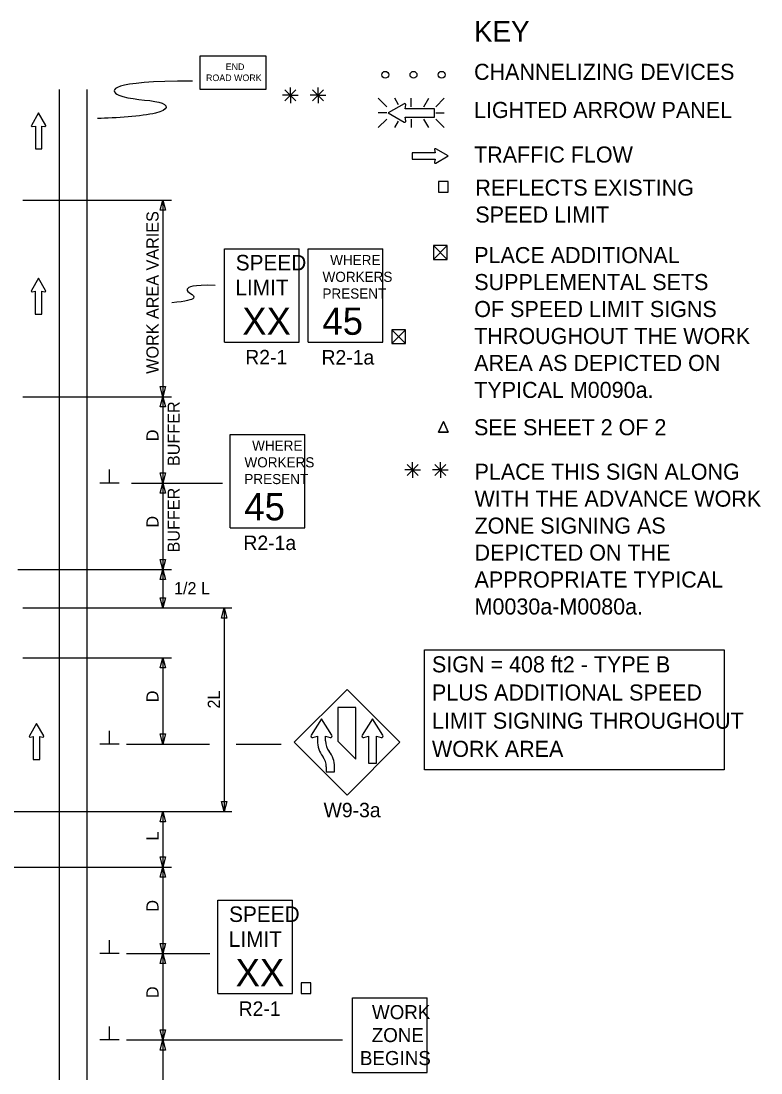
# Model space of a CAD drawing. Extents: x 16728 to 18482, y 5716 to 6919.
# Drawn here: x 17004 to 17432, y 6311 to 6919 of the extents above; entities that cross this region are included whole.
import ezdxf

# ---------------------------------------------------------------- set-up
doc = ezdxf.new("R2010")
doc.units = 0
for name, color, linetype in [('MT_SCRATCH_LEVEL_E', 7, 'Continuous'), ('PAVT_EDGE_EX', 7, 'Continuous'), ('TRAFFIC_SIGNS_PR', 7, 'Continuous'), ('TYPICAL_TEXT_DIMEN_EX', 7, 'Continuous'), ('TYPICAL_TEXT_DIMEN_PR', 7, 'Continuous')]:
    doc.layers.add(name, color=color, linetype=linetype)

msp = doc.modelspace()

# ---------------------------------------------------------------- linework, layer by layer
at = {"layer": 'MT_SCRATCH_LEVEL_E'}
for p, q in [((17014.23, 6866.09), (17010.12, 6858.85)), ((17018.37, 6858.85), (17014.23, 6866.09)), ((17010.6, 6858.17), (17012.38, 6858.48)), ((17012.38, 6858.48), (17012.38, 6845.23)), ((17016.12, 6845.23), (17016.12, 6858.48)), ((17016.12, 6858.48), (17017.9, 6858.17)), ((17012.38, 6845.23), (17016.12, 6845.23)), ((17243.66, 6843.03), (17230.4, 6843.03)), ((17230.4, 6843.03), (17230.4, 6839.29)), ((17243.34, 6844.81), (17243.66, 6843.03)), ((17251.27, 6841.18), (17244.03, 6845.29)), ((17230.4, 6839.29), (17243.66, 6839.29)), ((17243.66, 6839.29), (17243.34, 6837.51)), ((17244.03, 6837.03), (17251.27, 6841.18)), ((17014.19, 6770.46), (17010.08, 6763.22)), ((17018.34, 6763.22), (17014.19, 6770.46)), ((17010.56, 6762.53), (17012.34, 6762.85)), ((17012.34, 6762.85), (17012.34, 6749.59)), ((17016.08, 6749.59), (17016.08, 6762.85)), ((17016.08, 6762.85), (17017.86, 6762.53)), ((17012.34, 6749.59), (17016.08, 6749.59)), ((17013.05, 6512.79), (17008.94, 6505.55)), ((17017.2, 6505.55), (17013.05, 6512.79)), ((17009.42, 6504.87), (17011.2, 6505.19)), ((17011.2, 6505.19), (17011.2, 6491.93)), ((17014.94, 6491.93), (17014.94, 6505.19)), ((17014.94, 6505.19), (17016.72, 6504.87)), ((17011.2, 6491.93), (17014.94, 6491.93))]:
    msp.add_line(p, q, dxfattribs=at)
for centre, start, end in [((17010.52, 6858.63), 150.42484, 279.96381), ((17017.96, 6858.63), 260.03619, 29.77312), ((17243.8, 6844.88), 60.42484, 189.96381), ((17243.8, 6837.44), 170.03619, 299.77312), ((17010.49, 6762.99), 150.42484, 279.96381), ((17017.93, 6762.99), 260.03619, 29.77312), ((17009.35, 6505.33), 150.42484, 279.96381), ((17016.79, 6505.33), 260.03619, 29.77312)]:
    msp.add_arc(centre, 0.463, start, end, dxfattribs=at)
at = {"layer": 'PAVT_EDGE_EX'}
for p, q in [((17026.2, 6879.62), (17026.2, 6061.48)), ((17042.2, 6879.62), (17042.2, 6061.48))]:
    msp.add_line(p, q, dxfattribs=at)
at = {"layer": 'TRAFFIC_SIGNS_PR'}
for p, q in [((17210.76, 6874.56), (17215.69, 6869.63)), ((17222.52, 6870.74), (17220.32, 6874.57)), ((17229.84, 6869.63), (17229.84, 6874.57)), ((17237.08, 6869.63), (17239.93, 6874.57)), ((17243.99, 6869.63), (17248.93, 6874.57)), ((17215.69, 6866.08), (17210.76, 6866.08)), ((17243.99, 6866.08), (17248.93, 6866.08)), ((17210.76, 6857.59), (17215.69, 6862.52)), ((17220.27, 6857.59), (17222.39, 6861.25)), ((17229.84, 6862.52), (17229.84, 6857.59)), ((17239.97, 6857.59), (17237.12, 6862.52)), ((17243.99, 6862.52), (17248.93, 6857.58)), ((17121.81, 6787.43), (17165.01, 6787.43)), ((17121.81, 6733.43), (17121.81, 6787.43)), ((17165.01, 6733.43), (17165.01, 6787.43)), ((17170.22, 6787.32), (17213.42, 6787.32)), ((17170.22, 6733.32), (17170.22, 6787.32)), ((17213.42, 6733.32), (17213.42, 6787.32)), ((17121.81, 6733.43), (17165.01, 6733.43)), ((17170.22, 6733.32), (17213.42, 6733.32)), ((17125.05, 6679.98), (17168.25, 6679.98)), ((17125.05, 6625.98), (17125.05, 6679.98)), ((17168.25, 6625.98), (17168.25, 6679.98)), ((17125.05, 6625.98), (17168.25, 6625.98)), ((17192.71, 6532.45), (17162.17, 6501.9)), ((17223.26, 6501.9), (17192.71, 6532.45)), ((17187.41, 6522.07), (17187.41, 6502.5)), ((17197.77, 6522.07), (17187.41, 6522.07)), ((17197.77, 6492.14), (17197.77, 6522.07)), ((17162.17, 6501.9), (17192.71, 6471.35)), ((17187.41, 6502.5), (17197.77, 6492.14)), ((17192.71, 6471.35), (17223.26, 6501.9)), ((17117.97, 6410.43), (17161.17, 6410.43)), ((17117.97, 6356.43), (17117.97, 6410.43)), ((17161.17, 6356.43), (17161.17, 6410.43)), ((17117.97, 6356.43), (17161.17, 6356.43)), ((17195.86, 6310.89), (17195.86, 6354.09)), ((17195.86, 6354.09), (17239.06, 6354.09)), ((17239.06, 6310.89), (17239.06, 6354.09)), ((17195.86, 6310.89), (17239.06, 6310.89))]:
    msp.add_line(p, q, dxfattribs=at)
for points in [[(17107.51, 6879.72), (17145.91, 6879.72), (17145.91, 6898.92), (17107.51, 6898.92)], [(17245.62, 6820.15), (17251.21, 6820.15), (17251.21, 6826.32), (17245.62, 6826.32)], [(17166.19, 6356.43), (17171.78, 6356.43), (17171.78, 6362.6), (17166.19, 6362.6)]]:
    msp.add_lwpolyline(points, close=True, dxfattribs=at)
for points in [[(17225.77, 6871.35), (17216.48, 6866.08), (17225.77, 6860.75)], [(17226.65, 6861.38), (17226.25, 6863.65), (17243.26, 6863.65), (17243.26, 6868.45), (17226.25, 6868.45), (17226.65, 6870.73)], [(17248.42, 6687.54), (17245.63, 6681.37)], [(17245.63, 6681.37), (17248.42, 6687.54)], [(17251.22, 6681.37), (17248.42, 6687.54)], [(17248.42, 6687.54), (17251.22, 6681.37)], [(17245.63, 6681.37), (17251.22, 6681.37)], [(17251.22, 6681.37), (17245.63, 6681.37)], [(17183.93, 6506.07), (17177.94, 6515.48), (17171.95, 6506.07)], [(17213.43, 6506.07), (17207.45, 6515.48), (17201.45, 6506.07)], [(17172.99, 6504.65), (17175.58, 6505.36), (17175.57, 6502.85)], [(17180.29, 6502.73), (17180.3, 6505.36), (17182.88, 6504.65)], [(17202.5, 6504.65), (17205.09, 6505.36), (17205.09, 6489.83), (17209.81, 6489.83), (17209.81, 6505.36), (17212.39, 6504.65)], [(17180.71, 6487.71), (17180.71, 6484.73), (17185.43, 6484.73), (17185.43, 6487.71)]]:
    msp.add_lwpolyline(points, dxfattribs=at)
for centre in [(17214.83, 6888.11), (17231.13, 6888.11), (17247.43, 6888.11)]:
    msp.add_circle(centre, 2, dxfattribs=at)
for centre, radius, start, end in [((17226.06, 6870.83), 0.598, 350.73078, 118.89165), ((17226.06, 6861.28), 0.597, 241.48329, 9.95933), ((17172.74, 6505.56), 0.945, 147.52044, 285.3986), ((17189.74, 6502.43), 14.17, 178.32933, 218.54273), ((17168.48, 6503.1), 11.81, 358.18937, 0.00483), ((17189.74, 6502.43), 9.45, 178.19356, 218.54646), ((17183.13, 6505.56), 0.947, 254.68281, 32.2708), ((17179.76, 6493.25), 11.81, 74.67996, 74.68078), ((17193.89, 6512.4), 11.81, 212.45689, 212.46649), ((17202.25, 6505.56), 0.946, 147.54971, 285.33159), ((17212.64, 6505.56), 0.943, 254.67777, 32.46648), ((17223.4, 6512.4), 11.81, 212.45689, 212.46649), ((17171.26, 6487.71), 14.17, 0, 38.5422), ((17171.26, 6487.71), 9.45, 0, 38.54567)]:
    msp.add_arc(centre, radius, start, end, dxfattribs=at)
at = {"layer": 'TYPICAL_TEXT_DIMEN_EX'}
msp.add_lwpolyline([(17237.59, 6555.39), (17410.81, 6555.39), (17410.81, 6485.93), (17237.59, 6485.93)], close=True, dxfattribs=at)
at = {"layer": 'TYPICAL_TEXT_DIMEN_PR'}
for p, q in [((17156.71, 6879.43), (17163.09, 6873.05)), ((17163.09, 6879.43), (17156.71, 6873.05)), ((17159.9, 6876.24), (17159.9, 6880.69)), ((17172.78, 6879.43), (17179.15, 6873.05)), ((17179.15, 6879.43), (17172.78, 6873.05)), ((17175.96, 6876.24), (17175.96, 6880.69)), ((17159.9, 6876.24), (17155.37, 6876.24)), ((17159.9, 6876.24), (17163.09, 6876.24)), ((17159.9, 6876.24), (17164.38, 6876.24)), ((17159.9, 6876.24), (17159.9, 6871.74)), ((17175.96, 6876.24), (17171.43, 6876.24)), ((17175.96, 6876.24), (17179.15, 6876.24)), ((17175.96, 6876.24), (17180.44, 6876.24)), ((17175.96, 6876.24), (17175.96, 6871.74)), ((17005.13, 6815.59), (17091.2, 6815.59)), ((17084.63, 6809.72), (17086.2, 6815.59)), ((17086.2, 6815.59), (17086.2, 6701.86)), ((17086.2, 6815.59), (17087.77, 6809.72)), ((17086.2, 6809.72), (17084.63, 6809.72)), ((17087.77, 6809.72), (17086.2, 6809.72)), ((17242.63, 6789.28), (17250.63, 6781.28)), ((17242.63, 6781.28), (17250.63, 6789.28)), ((17218.57, 6732.53), (17226.57, 6740.53)), ((17218.58, 6740.53), (17226.57, 6732.53)), ((17005.13, 6701.86), (17091.2, 6701.86)), ((17086.2, 6701.86), (17084.63, 6707.72)), ((17084.63, 6707.72), (17086.2, 6707.72)), ((17084.63, 6696), (17086.2, 6701.86)), ((17086.2, 6707.72), (17087.77, 6707.72)), ((17087.77, 6707.72), (17086.2, 6701.86)), ((17086.2, 6701.86), (17086.2, 6651.86)), ((17086.2, 6701.86), (17087.77, 6696)), ((17086.2, 6696), (17084.63, 6696)), ((17087.77, 6696), (17086.2, 6696)), ((17055.32, 6651.86), (17055.32, 6659.65)), ((17230.63, 6659.45), (17226.1, 6659.45)), ((17227.44, 6662.63), (17233.82, 6656.26)), ((17233.82, 6662.63), (17227.44, 6656.26)), ((17230.63, 6659.45), (17230.63, 6663.9)), ((17230.63, 6659.45), (17233.82, 6659.45)), ((17230.63, 6659.45), (17235.11, 6659.45)), ((17230.63, 6659.45), (17230.63, 6654.95)), ((17246.69, 6659.45), (17242.16, 6659.45)), ((17249.88, 6662.63), (17243.5, 6656.26)), ((17243.51, 6662.63), (17249.88, 6656.26)), ((17246.69, 6659.45), (17246.69, 6663.9)), ((17246.69, 6659.45), (17249.88, 6659.45)), ((17246.69, 6659.45), (17251.17, 6659.45)), ((17246.69, 6659.45), (17246.69, 6654.95)), ((17086.2, 6651.86), (17084.63, 6657.72)), ((17084.63, 6657.72), (17086.2, 6657.72)), ((17086.2, 6657.72), (17087.77, 6657.72)), ((17087.77, 6657.72), (17086.2, 6651.86)), ((17060.95, 6651.86), (17049.7, 6651.86)), ((17068.03, 6651.86), (17120.65, 6651.86)), ((17084.63, 6646), (17086.2, 6651.86)), ((17086.2, 6651.86), (17086.2, 6601.86)), ((17086.2, 6651.86), (17087.77, 6646)), ((17086.2, 6646), (17084.63, 6646)), ((17087.77, 6646), (17086.2, 6646)), ((17086.2, 6601.86), (17084.63, 6607.72)), ((17084.63, 6607.72), (17086.2, 6607.72)), ((17086.2, 6607.72), (17087.77, 6607.72)), ((17087.77, 6607.72), (17086.2, 6601.86)), ((17002.25, 6601.86), (17091.2, 6601.86)), ((17084.63, 6596), (17086.2, 6601.86)), ((17086.2, 6601.86), (17086.2, 6579.61)), ((17086.2, 6601.86), (17087.77, 6596)), ((17086.2, 6596), (17084.63, 6596)), ((17087.77, 6596), (17086.2, 6596)), ((17086.2, 6579.61), (17084.63, 6585.48)), ((17084.63, 6585.48), (17086.2, 6585.48)), ((17086.2, 6585.48), (17087.77, 6585.48)), ((17087.77, 6585.48), (17086.2, 6579.61)), ((17005.13, 6579.61), (17126.01, 6579.61)), ((17120.11, 6573.75), (17121.68, 6579.61)), ((17121.68, 6579.61), (17121.68, 6461.74)), ((17121.68, 6579.61), (17123.25, 6573.75)), ((17121.68, 6573.75), (17120.11, 6573.75)), ((17123.25, 6573.75), (17121.68, 6573.75)), ((17005.13, 6550.81), (17091.2, 6550.81)), ((17084.63, 6544.95), (17086.2, 6550.81)), ((17086.2, 6550.81), (17086.2, 6500.81)), ((17086.2, 6550.81), (17087.77, 6544.95)), ((17086.2, 6544.95), (17084.63, 6544.95)), ((17087.77, 6544.95), (17086.2, 6544.95)), ((17055.32, 6500.81), (17055.32, 6508.59)), ((17060.95, 6500.81), (17049.7, 6500.81)), ((17065.2, 6500.81), (17113.17, 6500.81)), ((17086.2, 6500.81), (17084.63, 6506.67)), ((17084.63, 6506.67), (17086.2, 6506.67)), ((17086.2, 6506.67), (17087.77, 6506.67)), ((17087.77, 6506.67), (17086.2, 6500.81)), ((17128.55, 6500.81), (17154.51, 6500.81)), ((17121.68, 6461.74), (17120.11, 6467.6)), ((17120.11, 6467.6), (17121.68, 6467.6)), ((17121.68, 6467.6), (17123.25, 6467.6)), ((17123.25, 6467.6), (17121.68, 6461.74)), ((16981.95, 6461.74), (17126.01, 6461.74)), ((17084.63, 6455.88), (17086.2, 6461.74)), ((17086.2, 6461.74), (17086.2, 6429.63)), ((17086.2, 6461.74), (17087.77, 6455.88)), ((17086.2, 6455.88), (17084.63, 6455.88)), ((17087.77, 6455.88), (17086.2, 6455.88)), ((17086.2, 6429.63), (17084.63, 6435.5)), ((17084.63, 6435.5), (17086.2, 6435.5)), ((17086.2, 6435.5), (17087.77, 6435.5)), ((17087.77, 6435.5), (17086.2, 6429.63)), ((16962.6, 6429.63), (17091.2, 6429.63)), ((17084.63, 6423.77), (17086.2, 6429.63)), ((17086.2, 6429.63), (17086.2, 6379.63)), ((17086.2, 6429.63), (17087.77, 6423.77)), ((17086.2, 6423.77), (17084.63, 6423.77)), ((17087.77, 6423.77), (17086.2, 6423.77)), ((17055.32, 6379.63), (17055.32, 6387.42)), ((17086.2, 6379.63), (17084.63, 6385.5)), ((17084.63, 6385.5), (17086.2, 6385.5)), ((17086.2, 6385.5), (17087.77, 6385.5)), ((17087.77, 6385.5), (17086.2, 6379.63)), ((17060.95, 6379.63), (17049.7, 6379.63)), ((17065.2, 6379.63), (17113.37, 6379.63)), ((17084.63, 6373.77), (17086.2, 6379.63)), ((17086.2, 6379.63), (17087.77, 6373.77)), ((17086.2, 6379.63), (17086.2, 6329.63)), ((17086.2, 6373.77), (17084.63, 6373.77)), ((17087.77, 6373.77), (17086.2, 6373.77)), ((17055.32, 6329.63), (17055.32, 6337.42)), ((17086.2, 6329.63), (17084.63, 6335.5)), ((17084.63, 6335.5), (17086.2, 6335.5)), ((17086.2, 6335.5), (17087.77, 6335.5)), ((17087.77, 6335.5), (17086.2, 6329.63)), ((17060.95, 6329.63), (17049.7, 6329.63)), ((17065.2, 6329.63), (17190.08, 6329.63)), ((17084.63, 6323.77), (17086.2, 6329.63)), ((17086.2, 6329.63), (17086.2, 6279.63)), ((17086.2, 6329.63), (17087.77, 6323.77)), ((17086.2, 6323.77), (17084.63, 6323.77)), ((17087.77, 6323.77), (17086.2, 6323.77))]:
    msp.add_line(p, q, dxfattribs=at)
for points in [[(17242.63, 6789.28), (17242.63, 6781.28), (17250.63, 6781.28), (17250.63, 6789.28)], [(17218.58, 6740.53), (17218.57, 6732.53), (17226.57, 6732.53), (17226.57, 6740.53)]]:
    msp.add_lwpolyline(points, close=True, dxfattribs=at)
for points in [[(17103.23, 6884.48), (17054.77, 6884.48), (17054.77, 6873.73), (17089.68, 6873.73), (17089.68, 6864.91), (17058.47, 6863.08), (17048.43, 6862.81)], [(17116.5, 6766.15), (17103.11, 6766.78), (17098.45, 6763.56), (17102.22, 6761.63), (17105.93, 6758.89), (17099.99, 6756.98), (17091.3, 6756.24)]]:
    msp.add_open_spline(points, degree=3, dxfattribs=at)

# ---------------------------------------------------------------- texts
at = {"layer": 'TRAFFIC_SIGNS_PR'}
for s, height, p in [('END', 3.831, (17122.51, 6890.85)), ('ROAD WORK', 3.831, (17111.12, 6884.46)), ('PLACE ADDITIONAL', 9.3, (17266.28, 6779.13)), ('SPEED', 9, (17128.29, 6774.9)), ('WHERE', 5.85, (17182.94, 6777.96)), ('LIMIT', 9, (17128.11, 6760.5)), ('WORKERS', 5.85, (17178.52, 6768.29)), ('SUPPLEMENTAL SETS', 9.3, (17266.28, 6763.53)), ('PRESENT', 5.85, (17178.45, 6758.61)), ('OF SPEED LIMIT SIGNS', 9.3, (17266.28, 6747.93)), ('XX', 15.785, (17132.06, 6737.65)), ('45', 15.785, (17178.44, 6737.66)), ('THROUGHOUT THE WORK', 9.3, (17266.28, 6732.33)), ('R2-1', 8.37, (17133.82, 6720.56)), ('R2-1a', 8.37, (17177.93, 6720.45)), ('AREA AS DEPICTED ON', 9.3, (17266.28, 6716.73)), ('TYPICAL M0090a.', 9.3, (17266.28, 6701.13)), ('WHERE', 5.85, (17137.77, 6670.62)), ('WORKERS', 5.85, (17133.36, 6660.95)), ('PLACE THIS SIGN ALONG', 9.3, (17266.45, 6653.8)), ('PRESENT', 5.85, (17133.28, 6651.27)), ('WITH THE ADVANCE WORK', 9.3, (17266.45, 6638.2)), ('45', 15.785, (17133.27, 6630.31)), ('ZONE SIGNING AS', 9.3, (17266.45, 6622.6)), ('R2-1a', 8.37, (17132.76, 6613.11)), ('DEPICTED ON THE', 9.3, (17266.45, 6607)), ('APPROPRIATE TYPICAL', 9.3, (17266.45, 6591.4)), ('M0030a-M0080a.', 9.3, (17266.45, 6575.8)), ('W9-3a', 8.37, (17179.14, 6458.48)), ('SPEED', 9, (17124.46, 6397.9)), ('LIMIT', 9, (17124.28, 6383.5)), ('XX', 15.785, (17128.22, 6360.66)), ('R2-1', 8.37, (17129.98, 6343.56)), ('WORK', 8.119, (17207.11, 6341.67)), ('ZONE', 8.119, (17206.98, 6328.39)), ('BEGINS', 8.119, (17200.15, 6315.1))]:
    msp.add_text(s, height=height, dxfattribs=at).set_placement(p)
at = {"layer": 'TYPICAL_TEXT_DIMEN_EX'}
for s, height, p in [('KEY', 12, (17266.16, 6907.22)), ('CHANNELIZING DEVICES', 9.3, (17266.16, 6885.17)), ('LIGHTED ARROW PANEL', 9.3, (17266.16, 6863.12)), ('TRAFFIC FLOW', 9.3, (17266.16, 6837.32)), ('REFLECTS EXISTING', 9.3, (17266.91, 6818.2)), ('SPEED LIMIT', 9.3, (17266.91, 6802.6)), ('SEE SHEET 2 OF 2', 9.3, (17266.16, 6679.53)), ('SIGN = 408 ft2 - TYPE B', 9.3, (17241.81, 6542.32)), ('PLUS ADDITIONAL SPEED', 9.3, (17241.81, 6526.02)), ('LIMIT SIGNING THROUGHOUT', 9.3, (17241.81, 6509.72)), ('WORK AREA', 9.3, (17241.81, 6493.42))]:
    msp.add_text(s, height=height, dxfattribs=at).set_placement(p)
at = {"layer": 'TYPICAL_TEXT_DIMEN_PR'}
for s, p in [('WORK AREA VARIES', (17083.64, 6715.08)), ('BUFFER', (17095.91, 6661.72)), ('D', (17083.64, 6676.08)), ('BUFFER', (17095.91, 6611.72)), ('D', (17083.64, 6626.08)), ('D', (17083.64, 6525.03)), ('2L', (17119.12, 6521.4)), ('L', (17083.64, 6445.04)), ('D', (17083.64, 6403.85)), ('D', (17083.64, 6353.85))]:
    msp.add_text(s, height=7, rotation=90, dxfattribs=at).set_placement(p)
msp.add_text('1/2 L', height=7, dxfattribs=at).set_placement((17092.6, 6587.53))

doc.saveas('drawing.dxf')
